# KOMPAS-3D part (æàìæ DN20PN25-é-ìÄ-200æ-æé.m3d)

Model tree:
1. Объединить компоненты:1  (labels: СЕНС DN20PN25-В-НО-200С)
2. Эскиз:1
3. Операция выдавливания:1
     Расстояние 1 = 14
4. Фаска:1
     Угол = 45; Длина 1 = 2; Длина 2 = 2

Referenced files in D:\Савин\!СЕНСОР\3D для заказчика\!Новый перечень\СЕНС\7. СЕНС-В-НО-200С\DN20\: СЕНС DN20PN25-В-НО-200С.a3d
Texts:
  СЕНС DN20PN25-В-НО-200С-СВ
  ООО НПП Сенсор
  СЕНС DN20PN25-В-НО-200С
